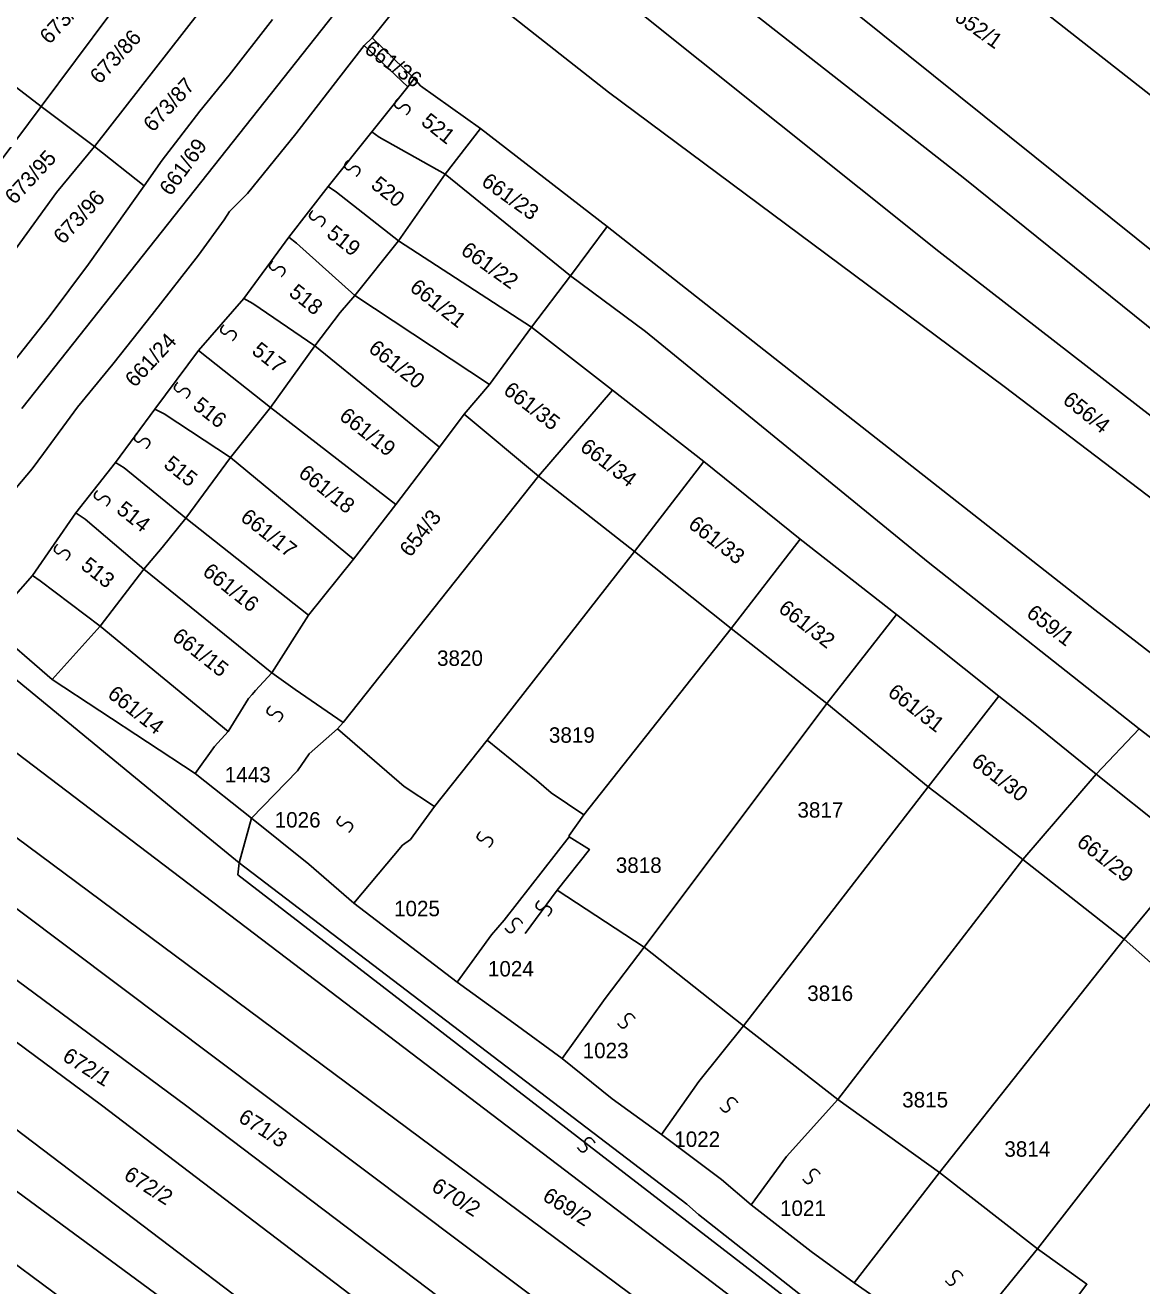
# Model space of a CAD drawing. Extents: x -581999 to -572728, y -1219553 to -1212032.
# Drawn here: x -577409.5 to -577264.7, y -1215188.7 to -1215025.3 of the extents above; entities that cross this region are included whole.
import ezdxf

# ---------------------------------------------------------------- set-up
doc = ezdxf.new("R2010")
doc.units = 0
for name, color, linetype in [('Vrstva 1', 7, 'Continuous'), ('Vrstva 2', 7, 'Continuous'), ('Vrstva 4', 7, 'Continuous'), ('Vrstva 6', 7, 'Continuous')]:
    doc.layers.add(name, color=color, linetype=linetype)

msp = doc.modelspace()

# ---------------------------------------------------------------- linework, layer by layer
at = {"layer": 'Vrstva 1'}
for p, q in [((-577308.6, -1215028.829), (-577343.316, -1215001.328)), ((-577349.154, -1215008.16), (-577291.038, -1215054.637)), ((-577356.151, -1215016.419), (-577364.501, -1215026.9)), ((-577365.924, -1215019.323), (-577409.937, -1215074.956)), ((-577279.6, -1215021.772), (-577229.838, -1215060.93)), ((-577365.551, -1215027.91), (-577368.834, -1215032.148)), ((-577364.501, -1215026.9), (-577365.551, -1215027.91)), ((-577365.551, -1215027.91), (-577359.875, -1215033.278)), ((-577287.685, -1215045.205), (-577308.6, -1215028.829)), ((-577368.834, -1215032.148), (-577374.394, -1215039.366)), ((-577374.394, -1215039.366), (-577380.693, -1215047.076)), ((-577243.04, -1215081.137), (-577287.685, -1215045.205)), ((-577380.693, -1215047.076), (-577383.023, -1215049.41)), ((-577383.023, -1215049.41), (-577383.691, -1215050.524)), ((-577383.691, -1215050.524), (-577387.028, -1215055.09)), ((-577291.038, -1215054.637), (-577236.783, -1215096.72)), ((-577387.028, -1215055.09), (-577393.03, -1215062.769)), ((-577393.03, -1215062.769), (-577398.142, -1215069.225)), ((-577343.844, -1215064.436), (-577333.36, -1215072.579)), ((-577385.772, -1215068.464), (-577387.014, -1215067.454)), ((-577398.142, -1215069.225), (-577402.699, -1215074.788)), ((-577377.711, -1215074.857), (-577385.772, -1215068.464)), ((-577342.948, -1215083.747), (-577333.36, -1215072.579)), ((-577333.36, -1215072.579), (-577321.521, -1215081.851)), ((-577402.699, -1215074.788), (-577407.146, -1215080.801)), ((-577407.146, -1215080.801), (-577408.591, -1215082.805)), ((-577330.512, -1215093.507), (-577321.521, -1215081.851)), ((-577321.521, -1215081.851), (-577309.033, -1215091.937)), ((-577408.591, -1215082.805), (-577412.258, -1215087.143)), ((-577317.961, -1215103.522), (-577309.033, -1215091.937)), ((-577309.033, -1215091.937), (-577296.545, -1215101.697)), ((-577408.545, -1215096.623), (-577407.555, -1215097.305)), ((-577407.555, -1215097.305), (-577399.799, -1215103.205)), ((-577305.567, -1215113.232), (-577296.545, -1215101.697)), ((-577296.545, -1215101.697), (-577283.247, -1215112.27)), ((-577377.519, -1215109.229), (-577374.505, -1215111.428)), ((-577374.505, -1215111.428), (-577368.292, -1215115.692)), ((-577292.412, -1215124.031), (-577283.247, -1215112.27)), ((-577283.247, -1215112.27), (-577278.819, -1215115.758)), ((-577278.819, -1215115.758), (-577270.647, -1215122.406)), ((-577270.647, -1215122.406), (-577265.083, -1215116.5)), ((-577280.161, -1215133.438), (-577270.647, -1215122.406)), ((-577270.647, -1215122.406), (-577257.834, -1215132.654)), ((-577267.009, -1215143.786), (-577257.834, -1215132.654)), ((-577322.196, -1215179.466), (-577293.895, -1215201.783))]:
    msp.add_line(p, q, dxfattribs=at)
for points in [[(-577190.642, -1215143.426), (-577202.916, -1215133.381), (-577221.737, -1215118.391), (-577282.573, -1215072.131), (-577333.871, -1215033.959), (-577356.151, -1215016.419)], [(-577394.08, -1215017.873), (-577407.43, -1215035.818)], [(-577400.53, -1215041), (-577386.885, -1215023.535)], [(-577377.444, -1215024.522), (-577383.069, -1215031.758), (-577386.847, -1215036.433), (-577391.739, -1215042.778), (-577394.076, -1215046.12)], [(-577301.594, -1215023.904), (-577255.623, -1215060.781), (-577238.92, -1215073.293), (-577187.022, -1215113.861), (-577170.099, -1215126.857), (-577131.679, -1215158.229), (-577103.813, -1215182.239)], [(-577364.501, -1215026.9), (-577359.073, -1215032.196)], [(-577407.43, -1215035.818), (-577414.423, -1215030.442)], [(-577364.551, -1215039.106), (-577359.875, -1215033.278), (-577359.073, -1215032.196)], [(-577359.073, -1215032.196), (-577358.253, -1215033.115), (-577350.468, -1215038.666)], [(-577407.43, -1215035.818), (-577417.45, -1215049.236)], [(-577407.43, -1215035.818), (-577400.53, -1215041)], [(-577370.213, -1215046.193), (-577364.551, -1215039.106)], [(-577355.047, -1215044.599), (-577363.605, -1215039.785), (-577364.551, -1215039.106)], [(-577350.468, -1215038.666), (-577355.047, -1215044.599)], [(-577350.468, -1215038.666), (-577334.068, -1215051.385)], [(-577410.764, -1215054.299), (-577405.452, -1215046.957), (-577400.53, -1215041)], [(-577394.076, -1215046.12), (-577400.53, -1215041)], [(-577355.047, -1215044.599), (-577361.083, -1215053.241)], [(-577338.808, -1215057.763), (-577355.047, -1215044.599)], [(-577394.076, -1215046.12), (-577401.305, -1215056.254), (-577406.371, -1215063.07), (-577412.928, -1215071.306)], [(-577375.326, -1215052.749), (-577370.213, -1215046.193)], [(-577361.083, -1215053.241), (-577369.119, -1215046.942), (-577370.213, -1215046.193)], [(-577338.808, -1215057.763), (-577334.068, -1215051.385)], [(-577334.068, -1215051.385), (-577305.62, -1215073.779), (-577270.825, -1215101.099), (-577229.558, -1215132.926), (-577212.647, -1215145.744), (-577207.511, -1215150.465), (-577185.738, -1215169.398)], [(-577381.17, -1215060.722), (-577375.326, -1215052.749)], [(-577366.744, -1215060.328), (-577374.309, -1215053.547), (-577375.326, -1215052.749)], [(-577361.083, -1215053.241), (-577366.744, -1215060.328)], [(-577343.844, -1215064.436), (-577361.083, -1215053.241)], [(-577343.844, -1215064.436), (-577338.808, -1215057.763)], [(-577190.451, -1215175.155), (-577218.161, -1215153.552), (-577224.903, -1215148.179), (-577254.304, -1215124.772), (-577265.083, -1215116.5), (-577292.449, -1215094.913), (-577329.082, -1215064.979), (-577338.808, -1215057.763)], [(-577387.014, -1215067.454), (-577381.17, -1215060.722)], [(-577371.933, -1215066.847), (-577379.985, -1215061.355), (-577381.17, -1215060.722)], [(-577366.744, -1215060.328), (-577368.674, -1215062.545), (-577371.933, -1215066.847)], [(-577349.324, -1215071.852), (-577366.744, -1215060.328)], [(-577349.324, -1215071.852), (-577343.844, -1215064.436)], [(-577392.675, -1215075.073), (-577387.014, -1215067.454)], [(-577371.933, -1215066.847), (-577377.711, -1215074.857)], [(-577355.786, -1215079.995), (-577371.933, -1215066.847)], [(-577352.58, -1215075.704), (-577349.324, -1215071.852)], [(-577397.789, -1215081.983), (-577392.675, -1215075.073)], [(-577382.898, -1215081.324), (-577391.5, -1215075.67), (-577392.675, -1215075.073)], [(-577377.711, -1215074.857), (-577382.898, -1215081.324)], [(-577361.448, -1215087.436), (-577377.711, -1215074.857)], [(-577355.786, -1215079.995), (-577352.58, -1215075.704)], [(-577342.948, -1215083.747), (-577352.58, -1215075.704)], [(-577361.448, -1215087.436), (-577355.786, -1215079.995)], [(-577397.789, -1215081.983), (-577402.926, -1215088.514)], [(-577388.659, -1215089.208), (-577396.689, -1215082.665), (-577397.789, -1215081.983)], [(-577382.898, -1215081.324), (-577388.659, -1215089.208)], [(-577366.927, -1215094.523), (-577382.898, -1215081.324)], [(-577369.001, -1215116.506), (-577368.292, -1215115.692), (-577342.948, -1215083.747)], [(-577330.512, -1215093.507), (-577342.948, -1215083.747)], [(-577402.926, -1215088.514), (-577408.545, -1215096.623)], [(-577402.926, -1215088.514), (-577402.902, -1215088.538), (-577401.717, -1215089.334), (-577394.136, -1215095.803)], [(-577366.927, -1215094.523), (-577361.448, -1215087.436)], [(-577388.659, -1215089.208), (-577391.743, -1215093.009), (-577394.136, -1215095.803)], [(-577372.771, -1215101.788), (-577388.659, -1215089.208)], [(-577349.609, -1215117.964), (-577330.512, -1215093.507)], [(-577317.961, -1215103.522), (-577330.512, -1215093.507)], [(-577372.771, -1215101.788), (-577366.927, -1215094.523)], [(-577408.545, -1215096.623), (-577414.226, -1215103.028)], [(-577394.136, -1215095.803), (-577399.799, -1215103.205)], [(-577394.136, -1215095.803), (-577377.519, -1215109.229)], [(-577377.519, -1215109.229), (-577372.771, -1215101.788)], [(-577414.226, -1215103.028), (-577406.008, -1215110.115)], [(-577399.799, -1215103.205), (-577406.008, -1215110.115)], [(-577399.799, -1215103.205), (-577383.18, -1215116.848)], [(-577337.054, -1215127.679), (-577317.961, -1215103.522)], [(-577305.567, -1215113.232), (-577317.961, -1215103.522)], [(-577418.143, -1215104.029), (-577389.858, -1215127.287), (-577381.778, -1215133.884), (-577323.721, -1215178.16), (-577322.196, -1215179.466)], [(-577300.768, -1215204.534), (-577317.65, -1215190.387), (-577375.626, -1215146.268), (-577423.256, -1215110.053)], [(-577406.008, -1215110.115), (-577387.473, -1215122.306)], [(-577380.087, -1215112.041), (-577379.644, -1215111.523), (-577377.519, -1215109.229)], [(-577383.18, -1215116.848), (-577380.532, -1215112.561), (-577380.087, -1215112.041)], [(-577329.256, -1215144.802), (-577305.567, -1215113.232)], [(-577292.412, -1215124.031), (-577305.567, -1215113.232)], [(-577431.474, -1215115.191), (-577321.671, -1215196.735)], [(-577372.694, -1215119.761), (-577369.001, -1215116.506)], [(-577369.001, -1215116.506), (-577360.371, -1215124.005)], [(-577387.473, -1215122.306), (-577384.976, -1215118.789), (-577383.18, -1215116.848)], [(-577356.418, -1215126.56), (-577349.609, -1215117.964)], [(-577349.609, -1215117.964), (-577343.199, -1215123.175)], [(-577380.178, -1215128.084), (-577374.202, -1215121.946), (-577372.694, -1215119.761)], [(-577320.787, -1215207.349), (-577435.857, -1215120.861)], [(-577387.473, -1215122.306), (-577380.178, -1215128.084)], [(-577343.199, -1215123.175), (-577341.299, -1215124.824)], [(-577360.371, -1215124.005), (-577356.418, -1215126.56)], [(-577341.299, -1215124.824), (-577337.054, -1215127.679)], [(-577316.388, -1215155), (-577292.412, -1215124.031)], [(-577287.501, -1215127.803), (-577292.412, -1215124.031)], [(-577359.528, -1215130.86), (-577356.418, -1215126.56)], [(-577440.423, -1215127.062), (-577388.73, -1215165.31), (-577326.044, -1215212.77)], [(-577380.178, -1215128.084), (-577372.709, -1215134.051)], [(-577338.981, -1215130.497), (-577338.98, -1215130.348), (-577337.054, -1215127.679)], [(-577280.161, -1215133.438), (-577287.501, -1215127.803)], [(-577360.561, -1215131.599), (-577359.528, -1215130.86)], [(-577347.417, -1215141.315), (-577338.981, -1215130.497)], [(-577340.537, -1215137.423), (-577336.351, -1215132.138), (-577338.981, -1215130.497)], [(-577330.598, -1215217.854), (-577399.612, -1215165.303), (-577444.075, -1215132.377)], [(-577366.892, -1215139.115), (-577360.561, -1215131.599)], [(-577372.709, -1215134.051), (-577366.892, -1215139.115)], [(-577304.12, -1215164.58), (-577280.161, -1215133.438)], [(-577267.009, -1215143.786), (-577280.161, -1215133.438)], [(-577340.537, -1215137.423), (-577329.256, -1215144.802)], [(-577366.892, -1215139.115), (-577353.493, -1215149.363)], [(-577448.458, -1215139.818), (-577322.598, -1215235.344)], [(-577349.045, -1215143.241), (-577347.417, -1215141.315)], [(-577353.493, -1215149.363), (-577349.045, -1215143.241)], [(-577290.961, -1215174.031), (-577267.009, -1215143.786)], [(-577255.183, -1215154.271), (-577267.009, -1215143.786)], [(-577326.319, -1215239.508), (-577351.684, -1215219.899), (-577453.207, -1215145.134)], [(-577334.289, -1215151.471), (-577329.256, -1215144.802)], [(-577329.256, -1215144.802), (-577316.388, -1215155)], [(-577353.493, -1215149.363), (-577346.135, -1215154.658)], [(-577457.59, -1215151.158), (-577356.931, -1215225.862), (-577330.999, -1215246.861)], [(-577339.876, -1215159.274), (-577334.289, -1215151.471)], [(-577278.247, -1215183.923), (-577255.183, -1215154.271)], [(-577346.135, -1215154.658), (-577339.876, -1215159.274)], [(-577322.159, -1215162.259), (-577316.388, -1215155)], [(-577316.388, -1215155), (-577304.12, -1215164.58)], [(-577339.876, -1215159.274), (-577333.387, -1215164.495)], [(-577327.02, -1215169.112), (-577322.159, -1215162.259)], [(-577333.387, -1215164.495), (-577327.02, -1215169.112)], [(-577310.788, -1215171.954), (-577304.12, -1215164.58)], [(-577304.12, -1215164.58), (-577290.961, -1215174.031)], [(-577327.02, -1215169.112), (-577319.227, -1215174.965)], [(-577315.389, -1215178.226), (-577310.788, -1215171.954)], [(-577319.227, -1215174.965), (-577315.389, -1215178.226)], [(-577302.003, -1215188.353), (-577290.961, -1215174.031)], [(-577290.961, -1215174.031), (-577278.247, -1215183.923)], [(-577315.389, -1215178.226), (-577307.599, -1215184.301)], [(-577307.599, -1215184.301), (-577302.003, -1215188.353)], [(-577284.476, -1215191.594), (-577278.247, -1215183.923)], [(-577278.247, -1215183.923), (-577271.85, -1215188.521), (-577277.92, -1215196.522)], [(-577302.003, -1215188.353), (-577298.491, -1215190.83)]]:
    msp.add_lwpolyline(points, dxfattribs=at)
at = {"layer": 'Vrstva 4'}
for p, q in [((-577380.178, -1215128.084), (-577381.778, -1215133.884)), ((-577381.778, -1215133.884), (-577381.929, -1215135.448)), ((-577381.929, -1215135.448), (-577287.529, -1215208.217)), ((-577344.66, -1215143.062), (-577340.537, -1215137.423))]:
    msp.add_line(p, q, dxfattribs=at)
at = {"layer": 'Vrstva 6'}
for points in [[(-577361.185, -1215034.835), (-577361.772, -1215035.457), (-577361.317, -1215036.066), (-577360.911, -1215036.054), (-577360.625, -1215035.749), (-577360.319, -1215035.595), (-577360.019, -1215035.611), (-577359.812, -1215035.713), (-577359.636, -1215035.916), (-577359.591, -1215036.28), (-577359.926, -1215036.792), (-577360.084, -1215036.884)], [(-577367.672, -1215042.805), (-577368.259, -1215043.427), (-577367.804, -1215044.036), (-577367.398, -1215044.024), (-577367.112, -1215043.719), (-577366.806, -1215043.565), (-577366.506, -1215043.581), (-577366.299, -1215043.683), (-577366.123, -1215043.886), (-577366.078, -1215044.25), (-577366.413, -1215044.762), (-577366.571, -1215044.854)], [(-577372.213, -1215049.312), (-577372.8, -1215049.934), (-577372.345, -1215050.543), (-577371.939, -1215050.531), (-577371.653, -1215050.226), (-577371.347, -1215050.072), (-577371.047, -1215050.088), (-577370.84, -1215050.19), (-577370.664, -1215050.393), (-577370.619, -1215050.757), (-577370.954, -1215051.269), (-577371.112, -1215051.361)], [(-577377.403, -1215055.819), (-577377.99, -1215056.441), (-577377.535, -1215057.05), (-577377.129, -1215057.038), (-577376.843, -1215056.733), (-577376.537, -1215056.579), (-577376.237, -1215056.595), (-577376.03, -1215056.697), (-577375.854, -1215056.9), (-577375.809, -1215057.264), (-577376.144, -1215057.776), (-577376.302, -1215057.868)], [(-577383.728, -1215064.115), (-577384.315, -1215064.737), (-577383.86, -1215065.346), (-577383.454, -1215065.334), (-577383.168, -1215065.029), (-577382.862, -1215064.875), (-577382.562, -1215064.891), (-577382.355, -1215064.993), (-577382.179, -1215065.196), (-577382.134, -1215065.56), (-577382.469, -1215066.072), (-577382.627, -1215066.164)], [(-577389.729, -1215071.597), (-577390.316, -1215072.219), (-577389.861, -1215072.828), (-577389.455, -1215072.816), (-577389.169, -1215072.511), (-577388.863, -1215072.357), (-577388.563, -1215072.373), (-577388.356, -1215072.475), (-577388.18, -1215072.678), (-577388.135, -1215073.042), (-577388.47, -1215073.554), (-577388.628, -1215073.646)], [(-577394.919, -1215078.104), (-577395.506, -1215078.726), (-577395.051, -1215079.335), (-577394.645, -1215079.323), (-577394.359, -1215079.018), (-577394.053, -1215078.864), (-577393.753, -1215078.88), (-577393.546, -1215078.982), (-577393.37, -1215079.185), (-577393.325, -1215079.549), (-577393.66, -1215080.061), (-577393.818, -1215080.153)], [(-577400.108, -1215085.587), (-577400.695, -1215086.209), (-577400.24, -1215086.818), (-577399.834, -1215086.806), (-577399.548, -1215086.501), (-577399.242, -1215086.347), (-577398.942, -1215086.363), (-577398.735, -1215086.465), (-577398.559, -1215086.668), (-577398.514, -1215087.032), (-577398.849, -1215087.544), (-577399.007, -1215087.636)], [(-577405.298, -1215092.582), (-577405.885, -1215093.204), (-577405.43, -1215093.813), (-577405.024, -1215093.801), (-577404.738, -1215093.496), (-577404.432, -1215093.342), (-577404.132, -1215093.358), (-577403.925, -1215093.46), (-577403.749, -1215093.663), (-577403.704, -1215094.027), (-577404.039, -1215094.539), (-577404.197, -1215094.631)], [(-577377.716, -1215113.537), (-577378.303, -1215114.159), (-577377.848, -1215114.768), (-577377.442, -1215114.756), (-577377.156, -1215114.451), (-577376.85, -1215114.297), (-577376.55, -1215114.313), (-577376.343, -1215114.415), (-577376.167, -1215114.618), (-577376.122, -1215114.982), (-577376.457, -1215115.494), (-577376.615, -1215115.586)], [(-577368.634, -1215127.852), (-577369.221, -1215128.474), (-577368.766, -1215129.083), (-577368.36, -1215129.071), (-577368.074, -1215128.766), (-577367.768, -1215128.612), (-577367.468, -1215128.628), (-577367.261, -1215128.73), (-577367.085, -1215128.933), (-577367.04, -1215129.297), (-577367.375, -1215129.809), (-577367.533, -1215129.901)], [(-577350.47, -1215129.804), (-577351.057, -1215130.426), (-577350.602, -1215131.035), (-577350.196, -1215131.023), (-577349.91, -1215130.718), (-577349.604, -1215130.564), (-577349.304, -1215130.58), (-577349.097, -1215130.682), (-577348.921, -1215130.885), (-577348.876, -1215131.249), (-577349.211, -1215131.761), (-577349.369, -1215131.853)], [(-577342.847, -1215138.75), (-577343.434, -1215139.372), (-577342.979, -1215139.981), (-577342.573, -1215139.969), (-577342.287, -1215139.664), (-577341.981, -1215139.51), (-577341.681, -1215139.526), (-577341.474, -1215139.628), (-577341.298, -1215139.831), (-577341.253, -1215140.195), (-577341.588, -1215140.707), (-577341.746, -1215140.799)], [(-577347.28, -1215142.358), (-577346.8, -1215143.065), (-577346.106, -1215142.754), (-577346.029, -1215142.354), (-577346.265, -1215142.009), (-577346.35, -1215141.677), (-577346.268, -1215141.387), (-577346.124, -1215141.207), (-577345.888, -1215141.079), (-577345.523, -1215141.115), (-577345.096, -1215141.554), (-577345.041, -1215141.727)], [(-577332.684, -1215154.721), (-577332.204, -1215155.428), (-577331.51, -1215155.117), (-577331.433, -1215154.717), (-577331.669, -1215154.372), (-577331.754, -1215154.04), (-577331.672, -1215153.75), (-577331.528, -1215153.57), (-577331.292, -1215153.442), (-577330.927, -1215153.478), (-577330.5, -1215153.917), (-577330.445, -1215154.09)], [(-577319.385, -1215165.62), (-577318.905, -1215166.327), (-577318.211, -1215166.016), (-577318.134, -1215165.616), (-577318.37, -1215165.271), (-577318.455, -1215164.939), (-577318.373, -1215164.649), (-577318.229, -1215164.469), (-577317.993, -1215164.341), (-577317.628, -1215164.377), (-577317.201, -1215164.816), (-577317.146, -1215164.989)], [(-577337.897, -1215170.804), (-577337.417, -1215171.511), (-577336.723, -1215171.2), (-577336.646, -1215170.8), (-577336.882, -1215170.455), (-577336.967, -1215170.123), (-577336.885, -1215169.833), (-577336.741, -1215169.653), (-577336.505, -1215169.525), (-577336.14, -1215169.561), (-577335.713, -1215170), (-577335.658, -1215170.173)], [(-577308.681, -1215174.892), (-577308.201, -1215175.599), (-577307.507, -1215175.288), (-577307.43, -1215174.888), (-577307.666, -1215174.543), (-577307.751, -1215174.211), (-577307.669, -1215173.921), (-577307.525, -1215173.741), (-577307.289, -1215173.613), (-577306.924, -1215173.649), (-577306.497, -1215174.088), (-577306.442, -1215174.261)], [(-577290.193, -1215188.068), (-577289.713, -1215188.775), (-577289.019, -1215188.464), (-577288.942, -1215188.064), (-577289.178, -1215187.719), (-577289.263, -1215187.387), (-577289.181, -1215187.097), (-577289.037, -1215186.917), (-577288.801, -1215186.789), (-577288.436, -1215186.825), (-577288.009, -1215187.264), (-577287.954, -1215187.437)]]:
    msp.add_open_spline(points, degree=2, dxfattribs=at)

# ---------------------------------------------------------------- texts
at = {"layer": 'Vrstva 2'}
for s, rotation, p in [('673/85', 47.27257, (-577406.356, -1215027.855)), ('652/1', 324.43923, (-577289.183, -1215024.548)), ('673/86', 47.27257, (-577399.848, -1215033.019)), ('661/36', 324.43923, (-577365.671, -1215028.713)), ('673/87', 47.27257, (-577392.928, -1215039.245)), ('521', 321.70279, (-577358.303, -1215038.061)), ('673/95', 47.27257, (-577410.874, -1215048.639)), ('661/69', 53.83619, (-577390.643, -1215047.522)), ('520', 321.70279, (-577364.813, -1215046.247)), ('661/23', 324.43923, (-577350.498, -1215045.904)), ('673/96', 47.27257, (-577404.582, -1215053.802)), ('519', 321.70279, (-577370.561, -1215052.592)), ('661/22', 324.43923, (-577353.159, -1215054.834)), ('518', 321.70279, (-577375.445, -1215060.223)), ('661/21', 321.70279, (-577359.776, -1215059.575)), ('661/24', 47.27257, (-577395.284, -1215072.353)), ('517', 321.70279, (-577380.255, -1215067.749)), ('661/20', 321.70279, (-577365.13, -1215067.482)), ('661/35', 322.31367, (-577347.639, -1215072.926)), ('516', 321.70279, (-577387.914, -1215074.878)), ('656/4', 321.37973, (-577275.115, -1215074.155)), ('661/19', 321.70279, (-577368.919, -1215076.254)), ('661/34', 322.31367, (-577337.702, -1215080.28)), ('515', 321.70279, (-577391.688, -1215082.488)), ('661/18', 321.70279, (-577374.207, -1215083.655)), ('514', 321.70279, (-577397.807, -1215088.379)), ('661/17', 321.70279, (-577381.733, -1215089.374)), ('654/3', 51.89165, (-577359.566, -1215094.371)), ('661/33', 322.31367, (-577323.673, -1215090.302)), ('513', 321.70279, (-577402.429, -1215095.635)), ('661/16', 321.70279, (-577386.636, -1215096.419)), ('661/32', 322.31367, (-577311.985, -1215101.21)), ('659/1', 322.31367, (-577279.824, -1215101.825)), ('661/15', 321.70279, (-577390.582, -1215104.841)), ('661/14', 321.70279, (-577398.959, -1215112.298)), ('661/31', 322.31367, (-577297.806, -1215112.087)), ('661/30', 322.31367, (-577286.965, -1215121.089)), ('661/29', 322.31367, (-577273.305, -1215131.529)), ('672/1', 327.71055, (-577404.813, -1215159.413)), ('671/3', 327.71055, (-577382.01, -1215167.339)), ('672/2', 327.71055, (-577396.855, -1215174.795)), ('670/2', 327.71055, (-577356.971, -1215176.295)), ('669/2', 327.71055, (-577342.563, -1215177.541))]:
    msp.add_text(s, height=2, rotation=rotation, dxfattribs=at).set_placement(p)
for s, p in [('3820', (-577356.105, -1215108.346)), ('3819', (-577341.598, -1215118.316)), ('1443', (-577383.624, -1215123.452)), ('3817', (-577309.378, -1215128.025)), ('1026', (-577377.153, -1215129.308)), ('3818', (-577332.927, -1215135.187)), ('1025', (-577361.679, -1215140.811)), ('1024', (-577349.508, -1215148.619)), ('3816', (-577308.107, -1215151.799)), ('1023', (-577337.22, -1215159.216)), ('3815', (-577295.795, -1215165.603)), ('1022', (-577325.347, -1215170.719)), ('3814', (-577282.548, -1215171.993)), ('1021', (-577311.635, -1215179.662))]:
    msp.add_text(s, height=2, dxfattribs=at).set_placement(p)

doc.saveas('drawing.dxf')
